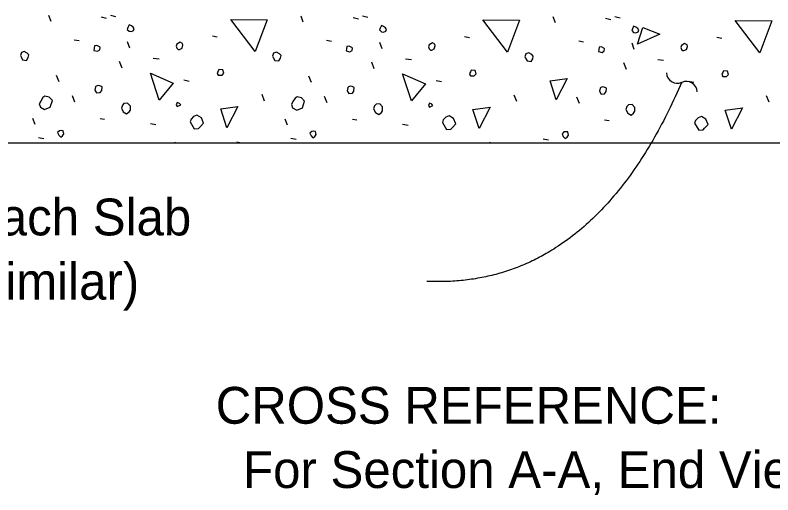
# Model space of a CAD drawing. Extents: x 0.5 to 40.8, y 1 to 25.8.
# Drawn here: x 29.406 to 33.558, y 8.632 to 11.259 of the extents above; entities that cross this region are included whole.
import ezdxf

# ---------------------------------------------------------------- set-up
doc = ezdxf.new("R2010")
doc.units = 0
for name, color, linetype in [('Dimension', 7, 'Continuous'), ('Miscellaneous', 7, 'Continuous'), ('TrafBarrierConc', 7, 'Continuous')]:
    doc.layers.add(name, color=color, linetype=linetype)

msp = doc.modelspace()

# ---------------------------------------------------------------- linework, layer by layer
at = {"layer": 'Dimension'}
for centre, start, end in [((33.0345, 10.9454), 182.36, 294.0872), ((33.0832, 10.8365), 2.36, 114.0872)]:
    msp.add_arc(centre, 0.0596, start, end, dxfattribs=at)
msp.add_open_spline([(33.0582, 10.8913), (32.57, 9.7607), (31.6609, 9.8003)], degree=2, dxfattribs=at)
at = {"layer": 'Miscellaneous'}
for p, q in [((29.6023, 11.2235), (29.5899, 11.2571)), ((29.9275, 11.2589), (29.9558, 11.2518)), ((30.9847, 11.22), (30.9723, 11.2536)), ((31.3099, 11.2553), (31.3382, 11.2483)), ((32.6923, 11.2518), (32.7206, 11.2447)), ((29.8763, 11.25), (29.9046, 11.243)), ((31.2587, 11.2465), (31.287, 11.2394)), ((32.3671, 11.2164), (32.3547, 11.25)), ((32.6411, 11.243), (32.6694, 11.2359)), ((30.4862, 11.1457), (30.5127, 11.1404)), ((31.8686, 11.1422), (31.8951, 11.1369)), ((33.251, 11.1387), (33.2775, 11.1334)), ((29.7296, 11.1245), (29.7561, 11.1192)), ((30.0336, 11.0786), (30.0212, 11.1121)), ((31.112, 11.121), (31.1385, 11.1157)), ((31.416, 11.075), (31.4036, 11.1086)), ((32.4943, 11.1174), (32.5209, 11.1121)), ((32.7984, 11.0715), (32.786, 11.1051)), ((29.9912, 10.969), (29.977, 11.0043)), ((30.1627, 11.0238), (30.1945, 11.0202)), ((31.5451, 11.0202), (31.5769, 11.0167)), ((32.9275, 11.0167), (32.9593, 11.0131)), ((31.3736, 10.9654), (31.3594, 11.0008)), ((32.756, 10.9619), (32.7418, 10.9972)), ((29.6465, 10.8929), (29.6323, 10.9283)), ((31.0289, 10.8894), (31.0147, 10.9248)), ((30.3306, 10.9053), (30.3589, 10.8982)), ((31.713, 10.9018), (31.7413, 10.8947)), ((33.0954, 10.8982), (33.1237, 10.8912)), ((29.7331, 10.7816), (29.719, 10.8169)), ((30.7725, 10.7886), (30.7584, 10.824)), ((31.1155, 10.778), (31.1013, 10.8134)), ((32.1549, 10.7851), (32.1408, 10.8205)), ((32.4979, 10.7745), (32.4837, 10.8099)), ((33.5373, 10.7816), (33.5232, 10.8169)), ((29.5157, 10.6596), (29.5033, 10.6932)), ((29.871, 10.6932), (29.8957, 10.6896)), ((30.8981, 10.6561), (30.8857, 10.6896)), ((31.2534, 10.6896), (31.2781, 10.6861)), ((32.6358, 10.6861), (32.6605, 10.6826)), ((30.1468, 10.6649), (30.1768, 10.6596)), ((31.5291, 10.6614), (31.5592, 10.6561)), ((29.5333, 10.5889), (29.5634, 10.5836)), ((30.2845, 10.5598), (30.2829, 10.5641)), ((30.6205, 10.5659), (30.645, 10.5598)), ((30.9157, 10.5853), (30.9458, 10.58)), ((31.6656, 10.5598), (31.6653, 10.5606)), ((32.0029, 10.5624), (32.0132, 10.5598)), ((32.2981, 10.5818), (32.3282, 10.5765))]:
    msp.add_line(p, q, dxfattribs=at)
for points in [[(30.7213, 11.0591), (30.5869, 11.2359), (30.7867, 11.2341), (30.7213, 11.0591)], [(32.1037, 11.0556), (31.9693, 11.2324), (32.1691, 11.2306), (32.1037, 11.0556)], [(33.4861, 11.052), (33.3517, 11.2288), (33.5515, 11.227), (33.4861, 11.052)], [(30.0301, 11.1705), (30.0425, 11.1687), (30.0548, 11.174), (30.0584, 11.1846), (30.0531, 11.1935), (30.0425, 11.2005), (30.0301, 11.2058), (30.023, 11.1917), (30.0195, 11.1811), (30.0301, 11.1705)], [(31.4125, 11.1669), (31.4248, 11.1652), (31.4372, 11.1705), (31.4408, 11.1811), (31.4355, 11.1899), (31.4248, 11.197), (31.4125, 11.2023), (31.4054, 11.1882), (31.4019, 11.1776), (31.4125, 11.1669)], [(32.7949, 11.1634), (32.8072, 11.1616), (32.8196, 11.1669), (32.8232, 11.1776), (32.8178, 11.1864), (32.8072, 11.1935), (32.7949, 11.1988), (32.7878, 11.1846), (32.7843, 11.174), (32.7949, 11.1634)], [(32.8161, 11.0998), (32.8444, 11.1917), (32.9381, 11.1546), (32.8161, 11.0998)], [(29.8374, 11.0662), (29.8568, 11.0609), (29.8692, 11.0697), (29.871, 11.0821), (29.8674, 11.0856), (29.8533, 11.0927), (29.8409, 11.0909), (29.8392, 11.0786), (29.8374, 11.0662)], [(30.2988, 11.0715), (30.3059, 11.0715), (30.32, 11.0786), (30.3253, 11.0945), (30.3235, 11.1033), (30.3094, 11.1104), (30.2917, 11.0998), (30.2882, 11.0892), (30.2917, 11.0786), (30.2988, 11.0715)], [(31.2198, 11.0626), (31.2392, 11.0573), (31.2516, 11.0662), (31.2534, 11.0786), (31.2498, 11.0821), (31.2357, 11.0892), (31.2233, 11.0874), (31.2216, 11.075), (31.2198, 11.0626)], [(31.6812, 11.0679), (31.6882, 11.0679), (31.7024, 11.075), (31.7077, 11.0909), (31.7059, 11.0998), (31.6918, 11.1068), (31.6741, 11.0962), (31.6706, 11.0856), (31.6741, 11.075), (31.6812, 11.0679)], [(32.6022, 11.0591), (32.6216, 11.0538), (32.634, 11.0626), (32.6358, 11.075), (32.6322, 11.0786), (32.6181, 11.0856), (32.6057, 11.0839), (32.6039, 11.0715), (32.6022, 11.0591)], [(33.0636, 11.0644), (33.0706, 11.0644), (33.0848, 11.0715), (33.0901, 11.0874), (33.0883, 11.0962), (33.0742, 11.1033), (33.0565, 11.0927), (33.053, 11.0821), (33.0565, 11.0715), (33.0636, 11.0644)], [(29.4379, 11.0308), (29.4467, 11.0149), (29.4679, 11.0114), (29.4768, 11.0273), (29.4803, 11.0414), (29.4715, 11.0503), (29.4556, 11.0591), (29.4396, 11.0538), (29.4343, 11.0379), (29.4379, 11.0308)], [(30.8203, 11.0273), (30.8291, 11.0114), (30.8503, 11.0078), (30.8592, 11.0238), (30.8627, 11.0379), (30.8539, 11.0467), (30.8379, 11.0556), (30.822, 11.0503), (30.8167, 11.0344), (30.8203, 11.0273)], [(32.2027, 11.0238), (32.2115, 11.0078), (32.2327, 11.0043), (32.2416, 11.0202), (32.2451, 11.0344), (32.2363, 11.0432), (32.2203, 11.052), (32.2044, 11.0467), (32.1991, 11.0308), (32.2027, 11.0238)], [(30.518, 10.9301), (30.5392, 10.9301), (30.5498, 10.9407), (30.5445, 10.9601), (30.5215, 10.9619), (30.518, 10.9513), (30.5127, 10.9424), (30.518, 10.9301), (30.5144, 10.9336)], [(30.1945, 10.7939), (30.1468, 10.9407), (30.2723, 10.8859), (30.1945, 10.7939)], [(31.5769, 10.7904), (31.5291, 10.9371), (31.6547, 10.8823), (31.5769, 10.7904)], [(31.9004, 10.9265), (31.9216, 10.9265), (31.9322, 10.9371), (31.9269, 10.9566), (31.9039, 10.9583), (31.9004, 10.9477), (31.8951, 10.9389), (31.9004, 10.9265), (31.8968, 10.9301)], [(33.2828, 10.923), (33.304, 10.923), (33.3146, 10.9336), (33.3093, 10.953), (33.2863, 10.9548), (33.2828, 10.9442), (33.2775, 10.9354), (33.2828, 10.923), (33.2792, 10.9265)], [(32.3703, 10.795), (32.3367, 10.8993), (32.4304, 10.9117), (32.3703, 10.795)], [(29.8427, 10.8487), (29.8515, 10.8328), (29.871, 10.8346), (29.8798, 10.847), (29.8816, 10.8664), (29.8692, 10.8717), (29.8604, 10.8735), (29.8498, 10.87), (29.8462, 10.8664), (29.8427, 10.8487)], [(31.2251, 10.8452), (31.2339, 10.8293), (31.2534, 10.8311), (31.2622, 10.8434), (31.264, 10.8629), (31.2516, 10.8682), (31.2428, 10.87), (31.2322, 10.8664), (31.2286, 10.8629), (31.2251, 10.8452)], [(32.6075, 10.8417), (32.6163, 10.8258), (32.6358, 10.8275), (32.6446, 10.8399), (32.6464, 10.8594), (32.634, 10.8647), (32.6252, 10.8664), (32.6146, 10.8629), (32.611, 10.8594), (32.6075, 10.8417)], [(29.5439, 10.7551), (29.5669, 10.7427), (29.597, 10.7551), (29.6094, 10.7922), (29.5917, 10.8099), (29.5687, 10.8152), (29.5581, 10.8081), (29.5457, 10.7886), (29.5369, 10.7727), (29.5439, 10.7551)], [(30.9263, 10.7515), (30.9493, 10.7391), (30.9794, 10.7515), (30.9917, 10.7886), (30.9741, 10.8063), (30.9511, 10.8116), (30.9405, 10.8046), (30.9281, 10.7851), (30.9193, 10.7692), (30.9263, 10.7515)], [(29.9877, 10.7498), (29.9983, 10.7285), (30.0159, 10.7179), (30.0301, 10.7285), (30.0372, 10.7391), (30.0372, 10.7604), (30.0212, 10.7763), (30.0018, 10.7745), (29.993, 10.7657), (29.9877, 10.7498)], [(30.2935, 10.7586), (30.3129, 10.7674), (30.3059, 10.7745), (30.2935, 10.7798), (30.2882, 10.7674), (30.2935, 10.7586)], [(30.5657, 10.6419), (30.5321, 10.7462), (30.6258, 10.7586), (30.5657, 10.6419)], [(31.37, 10.7462), (31.3807, 10.725), (31.3983, 10.7144), (31.4125, 10.725), (31.4195, 10.7356), (31.4195, 10.7568), (31.4036, 10.7727), (31.3842, 10.771), (31.3754, 10.7621), (31.37, 10.7462)], [(31.6759, 10.7551), (31.6953, 10.7639), (31.6882, 10.771), (31.6759, 10.7763), (31.6706, 10.7639), (31.6759, 10.7551)], [(31.9481, 10.6384), (31.9145, 10.7427), (32.0082, 10.7551), (31.9481, 10.6384)], [(32.7524, 10.7427), (32.763, 10.7215), (32.7807, 10.7109), (32.7949, 10.7215), (32.8019, 10.7321), (32.8019, 10.7533), (32.786, 10.7692), (32.7666, 10.7674), (32.7577, 10.7586), (32.7524, 10.7427)], [(33.3305, 10.6348), (33.2969, 10.7391), (33.3906, 10.7515), (33.3305, 10.6348)], [(30.3642, 10.6737), (30.3872, 10.6366), (30.4101, 10.6384), (30.419, 10.6472), (30.4384, 10.6667), (30.4261, 10.6967), (30.4013, 10.7109), (30.3836, 10.7038), (30.3695, 10.6896), (30.3642, 10.6737)], [(31.7466, 10.6702), (31.7696, 10.6331), (31.7925, 10.6348), (31.8014, 10.6437), (31.8208, 10.6631), (31.8085, 10.6932), (31.7837, 10.7073), (31.766, 10.7003), (31.7519, 10.6861), (31.7466, 10.6702)], [(33.129, 10.6667), (33.152, 10.6295), (33.1749, 10.6313), (33.1838, 10.6401), (33.2032, 10.6596), (33.1908, 10.6896), (33.1661, 10.7038), (33.1484, 10.6967), (33.1343, 10.6826), (33.129, 10.6667)], [(29.6447, 10.6013), (29.6553, 10.5907), (29.6659, 10.5977), (29.673, 10.6083), (29.6695, 10.626), (29.6606, 10.6278), (29.6482, 10.626), (29.6376, 10.6154), (29.6447, 10.6013)], [(31.0271, 10.5977), (31.0377, 10.5871), (31.0483, 10.5942), (31.0554, 10.6048), (31.0518, 10.6225), (31.043, 10.6242), (31.0306, 10.6225), (31.02, 10.6119), (31.0271, 10.5977)], [(32.4095, 10.5942), (32.4201, 10.5836), (32.4307, 10.5907), (32.4378, 10.6013), (32.4342, 10.6189), (32.4254, 10.6207), (32.413, 10.6189), (32.4024, 10.6083), (32.4095, 10.5942)]]:
    msp.add_lwpolyline(points, dxfattribs=at)
at = {"layer": 'TrafBarrierConc'}
msp.add_line((23.987, 10.5598), (39.8181, 10.5598), dxfattribs=at)

# ---------------------------------------------------------------- texts
at = {"layer": 'Dimension'}
for s, p in [('Approach Slab (Flexible Pavement Approach Slab ', (24.3764, 10.0525)), ('Shown, Rigid Pavement Approach Slab Similar)', (24.3764, 9.7005)), ('CROSS REFERENCE:', (30.5047, 9.021)), ('  For Section A-A, End View B-B and Detail "A" see Sheet 2.', (30.5047, 8.669))]:
    msp.add_text(s, height=0.2016, dxfattribs=at).set_placement(p)

doc.saveas('drawing.dxf')
